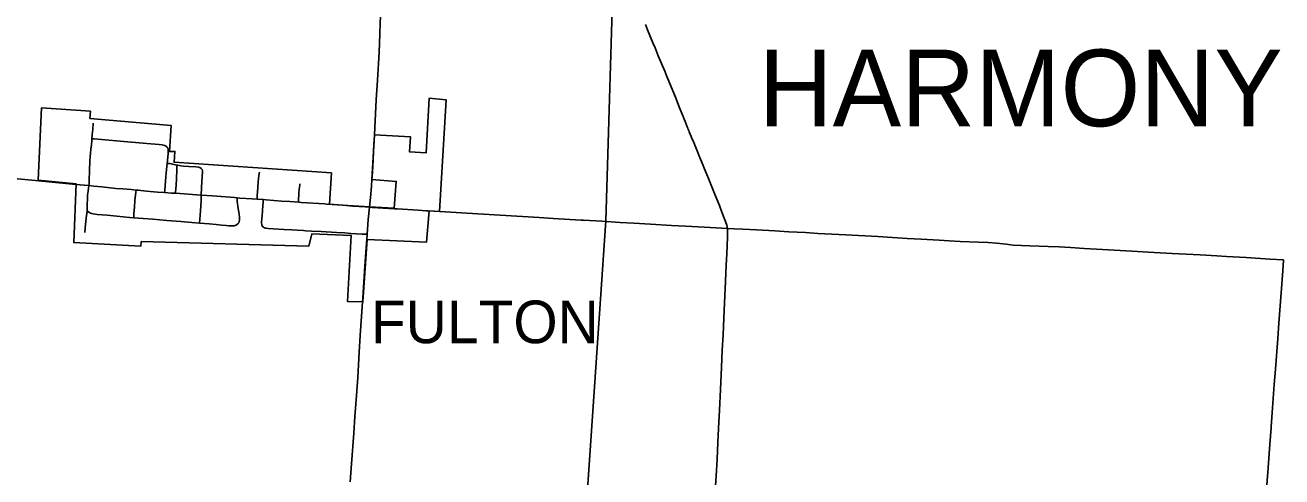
# Model space of a CAD drawing. Extents: x 9078 to 9739, y 4248 to 4966.
# Drawn here: x 9374.4 to 9448.2, y 4470.1 to 4496.6 of the extents above; entities that cross this region are included whole.
import ezdxf

# ---------------------------------------------------------------- set-up
doc = ezdxf.new("R2010")
doc.units = 0
for name, color, linetype in [('GM_X_City_Street', 7, 'Continuous'), ('GM_X_Corporation', 7, 'Continuous'), ('GM_X_Corporation_Text', 7, 'Continuous'), ('GM_X_County_Road', 7, 'Continuous'), ('GM_X_State_Route', 7, 'Continuous'), ('GM_X_Township', 7, 'Continuous'), ('GM_X_Township_Road', 7, 'Continuous'), ('GM_X_Township_Text', 7, 'Continuous')]:
    doc.layers.add(name, color=color, linetype=linetype)

msp = doc.modelspace()

# ---------------------------------------------------------------- linework, layer by layer
at = {"layer": 'GM_X_City_Street'}
for points in [[(9378.357, 4489.935), (9378.377, 4490.174), (9378.403, 4490.487), (9378.438, 4490.845)], [(9378.186, 4487.184), (9378.189, 4487.283), (9378.204, 4487.691), (9378.21, 4487.854), (9378.218, 4488.099), (9378.238, 4488.591), (9378.257, 4488.919), (9378.27, 4489.083), (9378.297, 4489.327), (9378.324, 4489.567), (9378.346, 4489.801), (9378.357, 4489.935)], [(9378.357, 4489.935), (9378.481, 4489.926), (9379.13, 4489.877), (9380.024, 4489.789), (9381.573, 4489.655), (9382.308, 4489.593), (9382.471, 4489.574), (9382.551, 4489.559), (9382.63, 4489.537), (9382.703, 4489.501), (9382.728, 4489.482), (9382.754, 4489.454)], [(9382.84, 4489.184), (9382.838, 4489.113), (9382.828, 4489.035), (9382.808, 4488.89), (9382.785, 4488.63), (9382.769, 4488.476)], [(9382.769, 4488.476), (9382.733, 4488.131), (9382.677, 4487.469), (9382.628, 4486.89), (9382.619, 4486.775)], [(9382.769, 4488.476), (9382.842, 4488.474), (9382.936, 4488.473), (9383.016, 4488.463), (9383.095, 4488.447), (9383.344, 4488.39)], [(9383.261, 4486.731), (9383.269, 4486.848), (9383.275, 4486.931), (9383.302, 4487.265), (9383.318, 4487.516), (9383.339, 4488.176), (9383.343, 4488.328), (9383.344, 4488.39)], [(9383.344, 4488.39), (9383.409, 4488.375), (9383.568, 4488.344), (9383.728, 4488.324), (9384.05, 4488.298), (9384.454, 4488.286), (9384.614, 4488.269), (9384.691, 4488.248), (9384.772, 4488.189)], [(9384.777, 4486.628), (9384.786, 4487.073), (9384.837, 4487.723), (9384.846, 4487.966), (9384.839, 4488.045), (9384.82, 4488.124), (9384.772, 4488.189)], [(9388.053, 4486.385), (9388.056, 4486.458), (9388.063, 4486.589), (9388.093, 4487.08), (9388.118, 4487.41), (9388.132, 4487.573), (9388.156, 4487.769), (9388.172, 4487.893), (9388.187, 4487.972)], [(9377.434, 4487.254), (9377.894, 4487.21), (9378.186, 4487.184)], [(9378.076, 4485.736), (9378.072, 4485.878), (9378.104, 4486.617), (9378.129, 4486.863), (9378.157, 4487.024), (9378.186, 4487.184)], [(9378.186, 4487.184), (9378.461, 4487.159), (9378.946, 4487.11), (9379.764, 4487.02), (9380.173, 4486.985), (9380.664, 4486.946), (9380.952, 4486.921)], [(9390.476, 4486.206), (9390.482, 4486.293), (9390.509, 4486.73), (9390.529, 4486.976), (9390.555, 4487.209), (9390.56, 4487.283)], [(9380.814, 4485.294), (9380.818, 4485.388), (9380.826, 4485.555), (9380.852, 4485.922), (9380.886, 4486.313), (9380.938, 4486.792), (9380.952, 4486.921)], [(9380.952, 4486.921), (9381.072, 4486.911), (9381.56, 4486.863), (9382.213, 4486.804), (9382.619, 4486.775)], [(9382.619, 4486.775), (9383.032, 4486.747), (9383.261, 4486.731)], [(9383.261, 4486.731), (9383.769, 4486.696), (9384.262, 4486.657), (9384.777, 4486.628)], [(9384.668, 4484.985), (9384.702, 4485.444), (9384.742, 4485.967), (9384.766, 4486.308), (9384.777, 4486.628)], [(9384.777, 4486.628), (9385.431, 4486.573), (9385.69, 4486.554), (9386.718, 4486.477), (9386.888, 4486.464)], [(9386.924, 4484.944), (9386.977, 4485.006), (9387.01, 4485.081), (9387.024, 4485.161), (9387.027, 4485.243), (9387.022, 4485.325), (9387.001, 4485.488), (9386.916, 4485.981), (9386.894, 4486.126), (9386.883, 4486.232), (9386.886, 4486.397), (9386.888, 4486.464)], [(9386.888, 4486.464), (9387.039, 4486.452), (9387.769, 4486.402), (9388.053, 4486.385)], [(9388.053, 4486.385), (9388.412, 4486.362)], [(9388.429, 4484.736), (9388.387, 4484.771), (9388.353, 4484.815), (9388.335, 4484.856), (9388.325, 4484.891), (9388.315, 4484.972), (9388.317, 4485.054), (9388.335, 4485.217), (9388.353, 4485.462), (9388.366, 4485.626), (9388.375, 4485.79), (9388.388, 4485.954), (9388.406, 4486.25), (9388.412, 4486.362)], [(9388.412, 4486.362), (9388.587, 4486.351), (9389.486, 4486.278), (9389.977, 4486.24), (9390.476, 4486.206)], [(9377.94, 4484.428), (9377.968, 4484.675), (9378.025, 4485.293), (9378.051, 4485.54), (9378.076, 4485.736)], [(9378.076, 4485.736), (9378.104, 4485.689), (9378.136, 4485.652), (9378.172, 4485.623), (9378.214, 4485.598), (9378.275, 4485.566), (9378.352, 4485.54), (9378.432, 4485.523), (9378.675, 4485.49), (9379.246, 4485.441), (9379.817, 4485.391), (9380.568, 4485.315), (9380.814, 4485.294)], [(9390.476, 4486.206), (9390.631, 4486.195), (9392.026, 4486.107), (9392.126, 4486.1)], [(9396.114, 4485.827), (9396.275, 4485.817), (9397.497, 4485.74), (9397.985, 4485.707), (9398.066, 4485.705)], [(9380.814, 4485.294), (9381.364, 4485.246), (9381.935, 4485.204), (9382.751, 4485.14), (9383.567, 4485.076), (9384.219, 4485.022), (9384.668, 4484.985)], [(9384.668, 4484.985), (9384.958, 4484.956), (9385.245, 4484.932), (9385.655, 4484.898), (9385.983, 4484.865), (9386.229, 4484.839), (9386.39, 4484.826), (9386.47, 4484.817), (9386.55, 4484.813), (9386.628, 4484.813), (9386.704, 4484.822), (9386.774, 4484.844), (9386.844, 4484.882), (9386.924, 4484.944)], [(9388.429, 4484.736), (9388.466, 4484.714), (9388.497, 4484.699), (9388.537, 4484.687), (9388.576, 4484.681), (9388.701, 4484.671), (9389.005, 4484.653), (9389.622, 4484.609), (9390.089, 4484.578), (9390.412, 4484.561), (9390.768, 4484.545), (9390.921, 4484.537), (9391.243, 4484.518), (9391.813, 4484.491), (9392.709, 4484.438), (9393.18, 4484.407), (9393.555, 4484.379), (9393.895, 4484.359), (9394.223, 4484.338), (9394.387, 4484.335), (9394.51, 4484.332)]]:
    msp.add_lwpolyline(points, dxfattribs=at)
at = {"layer": 'GM_X_Corporation'}
msp.add_lwpolyline([(9378.237, 4491.127), (9383.015, 4490.704), (9382.907, 4489.193), (9383.228, 4489.188), (9383.183, 4488.551), (9392.419, 4487.925), (9392.299, 4486.097), (9393.064, 4486.03), (9394.65, 4485.931), (9396.103, 4485.854), (9396.22, 4487.433), (9394.796, 4487.538), (9394.95, 4490.172), (9397.048, 4490.047), (9396.991, 4489.173), (9397.984, 4489.108), (9398.152, 4492.305), (9399.149, 4492.226), (9398.766, 4485.665), (9398.145, 4485.706), (9397.991, 4483.854), (9394.522, 4484.021), (9394.268, 4480.352), (9393.361, 4480.38), (9393.569, 4484.255), (9391.262, 4484.344), (9391.093, 4483.632), (9381.249, 4483.896), (9381.235, 4483.63), (9377.291, 4483.841), (9377.435, 4487.279), (9375.197, 4487.498), (9375.393, 4491.741), (9378.265, 4491.546)], close=True, dxfattribs=at)
at = {"layer": 'GM_X_County_Road'}
for points in [[(9368.184, 4488.123), (9369.014, 4488.046), (9370.32, 4487.925), (9372.116, 4487.756), (9373.259, 4487.646), (9373.993, 4487.575), (9375.054, 4487.485), (9375.216, 4487.47)], [(9375.216, 4487.47), (9375.823, 4487.406), (9377.226, 4487.273), (9377.434, 4487.254)], [(9392.126, 4486.1), (9393.102, 4486.028), (9393.672, 4485.984), (9394.403, 4485.932), (9394.641, 4485.917)], [(9394.641, 4485.917), (9394.809, 4485.907), (9395.461, 4485.868), (9396.114, 4485.827)], [(9398.066, 4485.705), (9398.771, 4485.661)], [(9398.771, 4485.661), (9401.008, 4485.522), (9402.318, 4485.441), (9404.609, 4485.304), (9405.428, 4485.257), (9407.065, 4485.157), (9407.207, 4485.15)], [(9407.207, 4485.15), (9408.294, 4485.093), (9409.357, 4485.022), (9410.172, 4484.979), (9411.152, 4484.922), (9412.379, 4484.848), (9413.198, 4484.809), (9413.935, 4484.767), (9415, 4484.705), (9415.669, 4484.671)], [(9414.918, 4468.998), (9414.99, 4470.144), (9415.048, 4471.127), (9415.101, 4472.11), (9415.142, 4472.93), (9415.189, 4473.995), (9415.253, 4475.224), (9415.314, 4476.536), (9415.359, 4477.519), (9415.401, 4478.421), (9415.439, 4479.405), (9415.483, 4480.306), (9415.523, 4481.126), (9415.588, 4482.522), (9415.618, 4483.175), (9415.659, 4484.158), (9415.669, 4484.486), (9415.669, 4484.671)], [(9415.669, 4484.671), (9416.064, 4484.65), (9416.555, 4484.629), (9417.374, 4484.583), (9418.437, 4484.523), (9419.254, 4484.477), (9420.236, 4484.422), (9420.972, 4484.38), (9422.61, 4484.291), (9424.494, 4484.194), (9426.213, 4484.088), (9427.031, 4484.037), (9428.095, 4483.977), (9428.668, 4483.939), (9429.322, 4483.903), (9430.388, 4483.868), (9430.962, 4483.839), (9431.453, 4483.799), (9432.024, 4483.737), (9432.431, 4483.696), (9432.921, 4483.661), (9433.412, 4483.64), (9434.478, 4483.608), (9435.133, 4483.581), (9435.788, 4483.544), (9436.607, 4483.497), (9437.671, 4483.434), (9439.391, 4483.335), (9440.701, 4483.261), (9441.765, 4483.201), (9442.585, 4483.159), (9443.403, 4483.11), (9444.385, 4483.054), (9444.958, 4483.02), (9446.104, 4482.954), (9447.496, 4482.875), (9448.303, 4482.826)], [(9447.574, 4473.033), (9447.634, 4473.874), (9447.759, 4475.509), (9447.827, 4476.409), (9447.962, 4478.208), (9448.029, 4479.108), (9448.181, 4481.152), (9448.274, 4482.461), (9448.303, 4482.826)], [(9446.815, 4462.765), (9446.846, 4463.245), (9446.893, 4463.899), (9446.967, 4464.88), (9447.035, 4465.861), (9447.094, 4466.597), (9447.155, 4467.414), (9447.16, 4467.488), (9447.203, 4468.076), (9447.214, 4468.229), (9447.278, 4469.132), (9447.369, 4470.358), (9447.496, 4471.993), (9447.569, 4472.974), (9447.574, 4473.033)]]:
    msp.add_lwpolyline(points, dxfattribs=at)
at = {"layer": 'GM_X_State_Route'}
for points in [[(9394.94, 4490.167), (9395.049, 4492.221), (9395.121, 4493.367), (9395.209, 4495.006), (9395.25, 4496.071), (9395.277, 4496.727), (9395.312, 4497.464), (9395.362, 4498.364), (9395.417, 4499.594), (9395.493, 4501.314), (9395.535, 4502.298), (9395.62, 4503.936), (9395.633, 4504.181), (9395.703, 4505.491), (9395.782, 4507.13), (9395.841, 4508.277), (9395.938, 4510.161), (9396.015, 4511.635), (9396.098, 4513.355), (9396.227, 4515.688)], [(9394.911, 4489.637), (9394.923, 4489.846), (9394.94, 4490.167)], [(9394.793, 4487.545), (9394.819, 4487.963), (9394.86, 4488.7), (9394.911, 4489.637)], [(9394.641, 4485.917), (9394.707, 4486.49), (9394.767, 4487.144), (9394.793, 4487.545)], [(9394.484, 4484.032), (9394.507, 4484.295), (9394.51, 4484.332), (9394.568, 4485.195), (9394.641, 4485.917)], [(9394.245, 4480.356), (9394.261, 4480.591), (9394.383, 4482.46), (9394.437, 4483.273), (9394.484, 4484.032)], [(9393.522, 4469.796), (9393.601, 4470.859), (9393.731, 4472.657), (9393.796, 4473.639), (9393.888, 4474.865), (9393.956, 4475.928), (9394.049, 4477.401), (9394.11, 4478.382), (9394.245, 4480.356)]]:
    msp.add_lwpolyline(points, dxfattribs=at)
at = {"layer": 'GM_X_Township'}
msp.add_lwpolyline([(9403.572, 4417.317), (9404.179, 4428.722), (9404.315, 4431.281), (9406.691, 4458.18), (9408.516, 4485.114), (9409.016, 4501.409), (9409.03, 4501.874), (9409.589, 4519.144), (9409.927, 4527.297), (9410.369, 4541.158), (9410.412, 4544.235), (9411.301, 4562.535), (9438.791, 4566.274), (9441.547, 4566.662)], dxfattribs=at)
at = {"layer": 'GM_X_Township_Road'}
for points in [[(9415.669, 4484.671), (9415.615, 4484.863), (9415.542, 4485.085), (9415.34, 4485.626), (9415.189, 4486.008), (9414.943, 4486.617), (9414.669, 4487.301), (9414.546, 4487.601), (9414.451, 4487.826), (9414.301, 4488.207), (9414.242, 4488.359), (9414.08, 4488.737), (9413.981, 4488.972), (9413.918, 4489.123), (9413.798, 4489.413), (9413.744, 4489.55), (9413.719, 4489.614), (9413.697, 4489.669), (9413.678, 4489.714), (9413.622, 4489.85), (9413.577, 4489.955), (9413.527, 4490.072), (9413.473, 4490.2), (9413.416, 4490.337), (9413.387, 4490.409), (9413.358, 4490.483), (9413.328, 4490.558), (9413.298, 4490.634), (9413.238, 4490.786), (9413.178, 4490.939), (9413.119, 4491.09), (9413.06, 4491.24), (9412.855, 4491.755), (9412.645, 4492.269), (9412.308, 4493.076), (9412.159, 4493.445), (9412.098, 4493.595), (9412.037, 4493.745), (9411.976, 4493.896), (9411.789, 4494.351), (9411.599, 4494.805), (9411.41, 4495.26), (9411.283, 4495.562), (9410.972, 4496.323), (9410.85, 4496.628)], [(9382.754, 4489.454), (9382.784, 4489.421), (9382.813, 4489.38), (9382.828, 4489.342), (9382.838, 4489.279), (9382.84, 4489.195), (9382.84, 4489.184)]]:
    msp.add_lwpolyline(points, dxfattribs=at)

# ---------------------------------------------------------------- texts
at = {"layer": 'GM_X_Corporation_Text'}
msp.add_text('FULTON', height=2.5, rotation=0.00001, dxfattribs=at).set_placement((9394.736, 4477.934))
at = {"layer": 'GM_X_Township_Text'}
msp.add_text('HARMONY', height=4.5, rotation=0.00001, dxfattribs=at).set_placement((9417.495, 4490.665))

doc.saveas('drawing.dxf')
